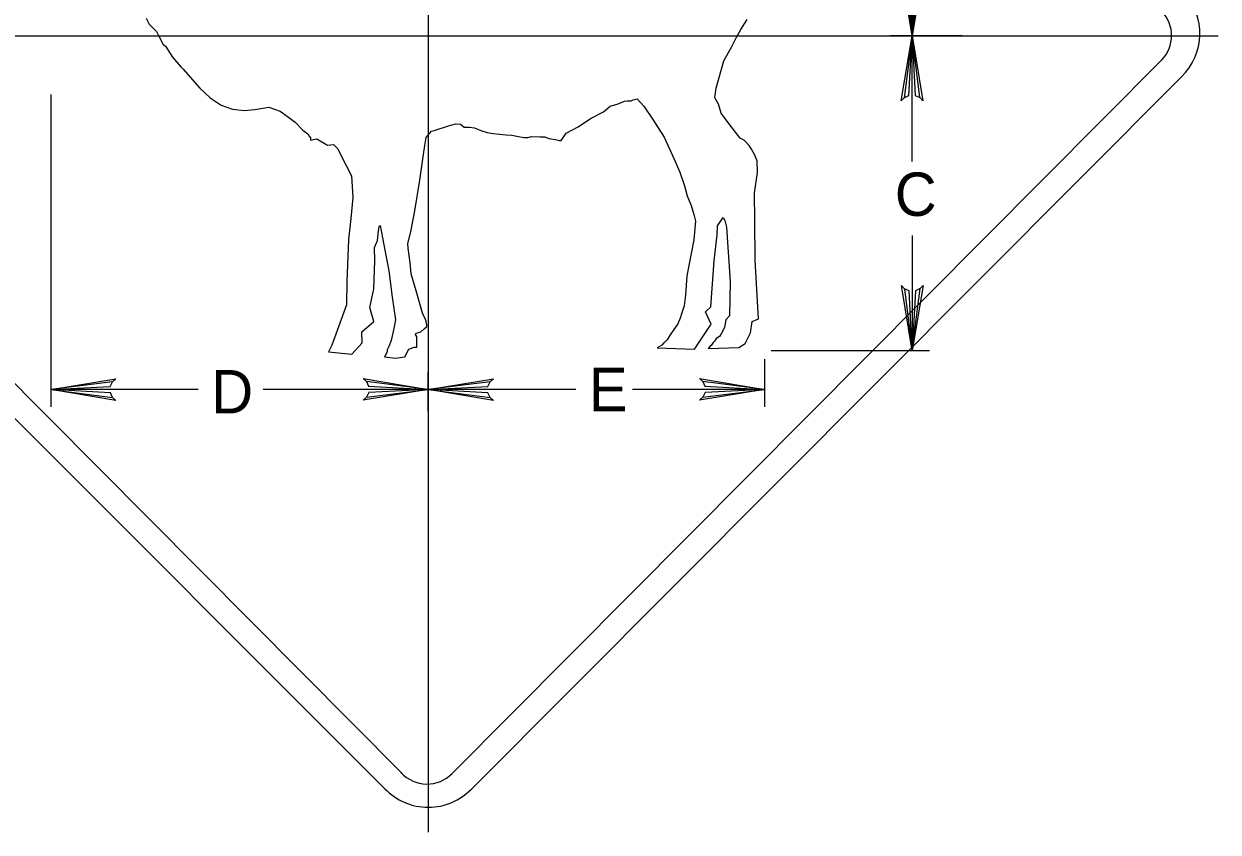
# Model space of a CAD drawing. Extents: x 0.013 to 0.184, y 0.005 to 0.259.
# Drawn here: x 0.0857 to 0.1545, y 0.1049 to 0.1514 of the extents above; entities that cross this region are included whole.
import ezdxf

# ---------------------------------------------------------------- set-up
doc = ezdxf.new("R2010")
doc.units = 0
doc.layers.add('11', color=7, linetype='Continuous')
doc.layers.add('3', color=7, linetype='Continuous')

# ---------------------------------------------------------------- blocks, each defined once
blk = doc.blocks.new('RARROW')
at = {"layer": '3'}
for p, q in [((-2.156, 0.28500000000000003), (-2.2665, 0.384625)), ((-2.2665, 0.384625), (0, 0)), ((0, 0), (-2.2665, -0.379125)), ((-2.156, 0.28500000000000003), (-2.075625, 0.12075)), ((0, 0), (-2.156, 0.28500000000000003)), ((-2.14975, -0.2705), (0, 0)), ((-2.075625, 0.12075), (0, 0)), ((0, 0), (-2.074, -0.108)), ((-2.2665, -0.379125), (-2.14975, -0.2705)), ((-2.074, -0.108), (-2.14975, -0.2705))]:
    blk.add_line(p, q, dxfattribs=at)

msp = doc.modelspace()

# ---------------------------------------------------------------- linework, layer by layer
at = {"layer": '11'}
for p, q in [((0.1065, 0.107375), (0.0655, 0.148375)), ((0.152375, 0.148375), (0.1115, 0.107375))]:
    msp.add_line(p, q, dxfattribs=at)
for centre, radius, start, end in [((0.1499707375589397, 0.1508906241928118), 0.0034797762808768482, 313.70333055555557, 42.689416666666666), ((0.10900000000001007, 0.10976662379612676), 0.0034597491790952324, 223.73079166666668, 316.2692055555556)]:
    msp.add_arc(centre, radius, start, end, dxfattribs=at)
at = {"layer": '3'}
for p, q in [((0.109, 0.196375), (0.109, 0.104875)), ((0.136875, 0.160375), (0.136875, 0.15075)), ((0.062375, 0.15075), (0.1545, 0.15075)), ((0.13975, 0.15075), (0.135625, 0.15075)), ((0.136875, 0.14350000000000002), (0.136875, 0.15075)), ((0.1075, 0.10825), (0.066625, 0.149375)), ((0.15125, 0.149375), (0.110375, 0.10825)), ((0.08725000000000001, 0.147375), (0.08725000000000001, 0.129375)), ((0.136875, 0.13925), (0.136875, 0.132625)), ((0.128375, 0.132125), (0.128375, 0.129375)), ((0.12875, 0.132625), (0.137875, 0.132625)), ((0.109, 0.129125), (0.109, 0.131375)), ((0.09575, 0.130375), (0.08725000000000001, 0.130375)), ((0.109, 0.130375), (0.09949013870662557, 0.130375)), ((0.11750000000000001, 0.130375), (0.109, 0.130375)), ((0.128375, 0.130375), (0.12076672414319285, 0.130375)), ((0.1074337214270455, 0.10829953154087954), (0.1075, 0.10825))]:
    msp.add_line(p, q, dxfattribs=at)
for points in [[(0.09274241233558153, 0.15177024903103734), (0.09292455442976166, 0.15142787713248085), (0.09333437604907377, 0.15099420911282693), (0.09349375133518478, 0.1506974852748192), (0.0937214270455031, 0.1502409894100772), (0.09385803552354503, 0.15014969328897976), (0.09426785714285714, 0.14951320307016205), (0.09474598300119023, 0.14896540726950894), (0.09488258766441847, 0.1488284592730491), (0.09583883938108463, 0.14773287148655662), (0.09643080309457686, 0.1471850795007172)], [(0.12603437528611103, 0.14931789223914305), (0.12646696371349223, 0.15009393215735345), (0.1267401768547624, 0.15064172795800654), (0.12701339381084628, 0.15112104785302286), (0.12737767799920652, 0.15169166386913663)], [(0.1093401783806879, 0.14529659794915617), (0.11016517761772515, 0.14557049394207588), (0.11057499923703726, 0.14568461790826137), (0.11084821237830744, 0.145661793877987), (0.11107589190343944, 0.14547919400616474), (0.1113718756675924, 0.14547919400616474), (0.11166785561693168, 0.14545636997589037), (0.1120321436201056, 0.14529659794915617), (0.11239642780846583, 0.14518247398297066), (0.11273794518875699, 0.14511399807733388), (0.11310223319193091, 0.14509117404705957), (0.11346651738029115, 0.14504552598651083), (0.1138080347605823, 0.14502270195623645), (0.11410401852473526, 0.14497705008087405), (0.11451384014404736, 0.1448857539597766), (0.11474151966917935, 0.1448857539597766), (0.11494642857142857, 0.14495422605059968), (0.11542455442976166, 0.1449314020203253), (0.11572053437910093, 0.1449314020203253), (0.11594821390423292, 0.1448401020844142), (0.11633526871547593, 0.1447716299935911), (0.11656294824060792, 0.1447259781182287), (0.11665401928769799, 0.1447259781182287), (0.11694999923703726, 0.14513682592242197), (0.11763303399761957, 0.14550202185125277), (0.11833883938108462, 0.14598134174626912), (0.11909017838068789, 0.14636936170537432), (0.1194772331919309, 0.14668890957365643), (0.1199325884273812, 0.1468258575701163), (0.12029687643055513, 0.1469856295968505), (0.12045625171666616, 0.14700845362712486), (0.12068392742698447, 0.14700845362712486), (0.12079776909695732, 0.14705410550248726), (0.12102544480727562, 0.14712257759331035), (0.12141249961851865, 0.14668890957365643), (0.1219361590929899, 0.14593568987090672), (0.1225964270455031, 0.14490857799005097), (0.12316562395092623, 0.1436532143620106), (0.1234843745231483, 0.14289999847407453), (0.12375758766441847, 0.1421011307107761), (0.1239169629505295, 0.14153051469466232), (0.12414464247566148, 0.14098271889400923), (0.12430401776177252, 0.14045775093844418), (0.12439508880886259, 0.1400697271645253), (0.12430401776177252, 0.13899696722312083), (0.1238941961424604, 0.13691991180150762), (0.12382589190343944, 0.13580149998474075), (0.12373482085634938, 0.13518523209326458), (0.12359821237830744, 0.13479721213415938), (0.12350714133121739, 0.13447766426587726), (0.12337053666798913, 0.13415811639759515), (0.12314285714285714, 0.13383857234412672), (0.12293794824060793, 0.1335190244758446), (0.12275580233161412, 0.13324512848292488), (0.122573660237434, 0.13306252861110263), (0.12245982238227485, 0.13292558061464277), (0.12218660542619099, 0.13276580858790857), (0.12432678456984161, 0.1326973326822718), (0.12530580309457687, 0.13413529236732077), (0.12496428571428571, 0.1348428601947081), (0.12528303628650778, 0.13513958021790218), (0.12546517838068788, 0.13778725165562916), (0.125647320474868, 0.1392936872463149), (0.1256700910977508, 0.1397958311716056), (0.12598883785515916, 0.14027515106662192), (0.1260799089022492, 0.1401153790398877), (0.12617098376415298, 0.1397273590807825), (0.12639865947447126, 0.13657753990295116), (0.12635312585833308, 0.13461461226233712), (0.12614821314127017, 0.13438636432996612), (0.12605714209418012, 0.1339526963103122), (0.12587500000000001, 0.13358750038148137), (0.12578392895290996, 0.13342772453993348), (0.12557901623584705, 0.13331360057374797), (0.12548794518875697, 0.13315382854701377), (0.125419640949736, 0.133085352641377), (0.12530580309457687, 0.13290275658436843), (0.1252374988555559, 0.13287993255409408), (0.12512366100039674, 0.1327429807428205), (0.12689955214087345, 0.13278863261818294), (0.12726384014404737, 0.1330168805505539), (0.12755982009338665, 0.1336331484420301), (0.1276508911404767, 0.134295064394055), (0.12801517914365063, 0.1344548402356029), (0.12783303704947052, 0.13783290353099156), (0.12781026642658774, 0.1401153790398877), (0.12778749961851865, 0.14169028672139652), (0.12796964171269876, 0.14287717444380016), (0.12794687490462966, 0.14353909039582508), (0.12778749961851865, 0.1439042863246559), (0.1276281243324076, 0.14422383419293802), (0.12749151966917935, 0.14442925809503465), (0.1272183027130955, 0.1447259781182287), (0.1269678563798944, 0.14486292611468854), (0.12637589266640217, 0.14561614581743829), (0.12587500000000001, 0.14630088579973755), (0.12571562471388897, 0.14680303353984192), (0.12555624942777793, 0.14707692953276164), (0.12551071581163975, 0.1471910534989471), (0.12557901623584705, 0.14773884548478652), (0.12603437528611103, 0.14931789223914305)], [(0.09643080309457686, 0.1471850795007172), (0.09706830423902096, 0.14675140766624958), (0.09772857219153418, 0.1465231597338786), (0.09838884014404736, 0.1464546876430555), (0.09900357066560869, 0.14650033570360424), (0.09982321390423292, 0.1466372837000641), (0.10046071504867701, 0.1464090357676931), (0.10093884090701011, 0.1460666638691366), (0.10132589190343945, 0.14576994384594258), (0.10178125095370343, 0.1453134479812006), (0.1020544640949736, 0.14510802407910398), (0.10214553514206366, 0.14497107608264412), (0.10221383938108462, 0.144879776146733), (0.10221383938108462, 0.14474282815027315), (0.10257812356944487, 0.14481130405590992), (0.10319285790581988, 0.1444461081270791), (0.10353437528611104, 0.1444917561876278), (0.10378482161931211, 0.14424068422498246), (0.10396696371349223, 0.14387548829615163), (0.10458169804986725, 0.142688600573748), (0.10464999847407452, 0.14143324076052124), (0.10453616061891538, 0.14022352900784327), (0.10439955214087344, 0.13901381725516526), (0.10430848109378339, 0.1366003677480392), (0.10428571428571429, 0.13525370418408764), (0.10383035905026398, 0.13397552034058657), (0.10344330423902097, 0.13292558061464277), (0.10326116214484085, 0.1325375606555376), (0.10460446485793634, 0.13240061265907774), (0.10519642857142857, 0.13306252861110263), (0.10517366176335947, 0.1337016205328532), (0.10585669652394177, 0.134295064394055), (0.10562901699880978, 0.13509393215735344), (0.10585669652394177, 0.13616669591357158), (0.10592500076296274, 0.13778725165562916), (0.10590223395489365, 0.13856329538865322), (0.10608437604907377, 0.13895131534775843), (0.10612990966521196, 0.13952193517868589), (0.10617544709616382, 0.13977300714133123), (0.10622098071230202, 0.13981865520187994), (0.106448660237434, 0.13870024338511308), (0.10672187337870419, 0.1372166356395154), (0.10692678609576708, 0.13568737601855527), (0.1071089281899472, 0.13438636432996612), (0.10701785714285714, 0.13388422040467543), (0.10685848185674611, 0.13319947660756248), (0.10672187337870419, 0.13285710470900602), (0.10663080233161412, 0.13265168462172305), (0.10663080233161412, 0.1325375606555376), (0.1064714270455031, 0.13226366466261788), (0.1071089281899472, 0.13217236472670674), (0.10765535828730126, 0.13226366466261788), (0.10788303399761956, 0.1326973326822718), (0.10817901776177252, 0.1328114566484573), (0.10833839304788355, 0.1328114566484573), (0.10833839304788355, 0.13342772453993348), (0.10827008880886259, 0.1335190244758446), (0.10829285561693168, 0.13361032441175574), (0.10856607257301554, 0.1337016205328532), (0.10877098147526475, 0.13386139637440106), (0.10890758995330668, 0.13399834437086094), (0.10890758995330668, 0.13406682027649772), (0.10888482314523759, 0.13431789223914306), (0.10879374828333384, 0.13450048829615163), (0.1086799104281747, 0.13470591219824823), (0.10829285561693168, 0.1360525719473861), (0.10801964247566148, 0.1370340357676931), (0.10795133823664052, 0.13767313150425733), (0.10783750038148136, 0.13851764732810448), (0.10781473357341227, 0.1387915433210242), (0.10799687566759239, 0.1394534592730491), (0.10822455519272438, 0.14066317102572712), (0.10852053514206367, 0.14244350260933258), (0.10872544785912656, 0.1439042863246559), (0.10879374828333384, 0.14442925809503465), (0.10888482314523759, 0.1448857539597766), (0.10906696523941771, 0.14511399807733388), (0.10918080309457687, 0.14525094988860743), (0.1093401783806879, 0.14529659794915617)]]:
    msp.add_lwpolyline(points, dxfattribs=at)
for centre, radius, start, end in [((0.14984518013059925, 0.15076449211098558), 0.0019759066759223, 315.3142833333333, 44.30036944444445), ((0.10892805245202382, 0.10968165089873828), 0.002035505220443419, 222.7660472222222, 315.3044611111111)]:
    msp.add_arc(centre, radius, start, end, dxfattribs=at)

# ---------------------------------------------------------------- block references
at = {"layer": '3', "xscale": 0.0016545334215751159, "yscale": 0.0016366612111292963}
for p, rotation in [((0.136875, 0.15075), -90), ((0.136875, 0.15075), 90), ((0.136875, 0.132625), -90), ((0.08725000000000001, 0.130375), 180), ((0.109, 0.130375), 180)]:
    msp.add_blockref('RARROW', p, dxfattribs=dict(at, rotation=rotation))
for p in [(0.109, 0.130375), (0.128375, 0.130375)]:
    msp.add_blockref('RARROW', p, dxfattribs=at)

# ---------------------------------------------------------------- texts
at = {"layer": '3'}
for s, p in [('C', (0.135875, 0.140375)), ('D', (0.0965, 0.129)), ('E', (0.11825000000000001, 0.129125))]:
    msp.add_text(s, height=0.0024997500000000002, dxfattribs=at).set_placement(p)

doc.saveas('drawing.dxf')
